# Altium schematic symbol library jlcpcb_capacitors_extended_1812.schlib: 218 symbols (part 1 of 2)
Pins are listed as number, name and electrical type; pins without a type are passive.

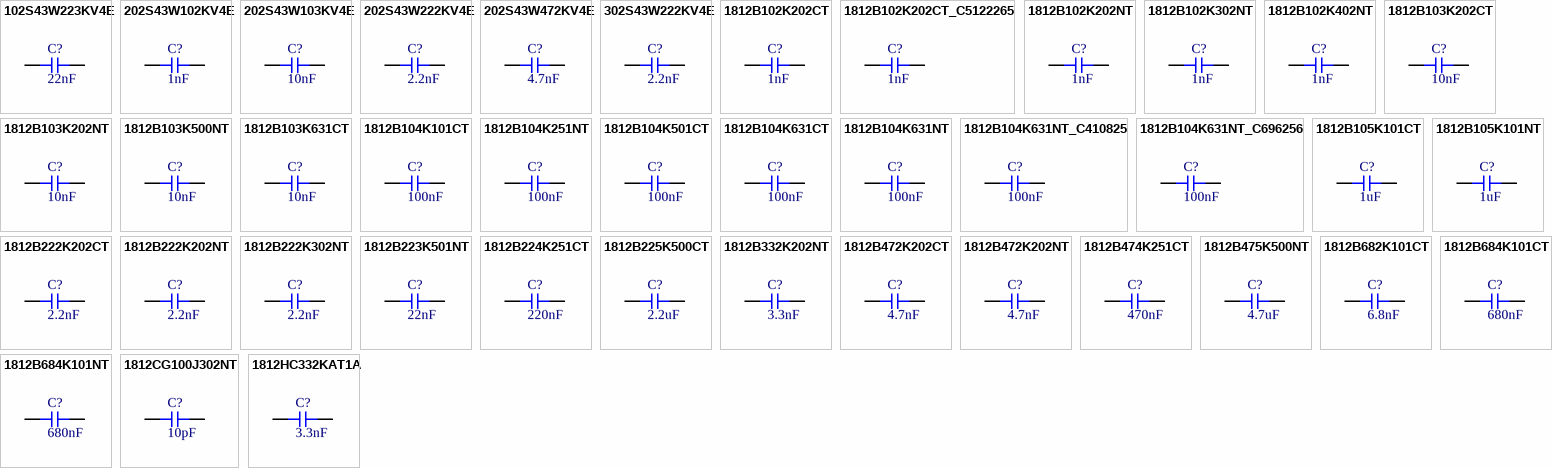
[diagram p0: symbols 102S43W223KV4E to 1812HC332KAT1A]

## 102S43W223KV4E
designator C?  Capacitance: 22nF  (hidden comment: *)
Capacitor, Ceramic (MLCC), 22nF, ±10%, 1kV, X7R, ±10%, SMD 1812; Manufacturer: Johanson Dielectrics; Manufacturer Part Number: 102S43W223KV4E
footprint CAP-1812 (1812 (4532M) Capacitor)
pins: 1, 2

## 202S43W102KV4E
designator C?  Capacitance: 1nF  (hidden comment: *)
Capacitor, Ceramic (MLCC), 1nF, ±10%, 2kV, X7R, ±10%, SMD 1812; Manufacturer: Johanson Dielectrics; Manufacturer Part Number: 202S43W102KV4E
footprint CAP-1812 (1812 (4532M) Capacitor)
pins: 1, 2

## 202S43W103KV4E
designator C?  Capacitance: 10nF  (hidden comment: *)
Capacitor, Ceramic (MLCC), 10nF, ±10%, 2kV, X7R, ±10%, SMD 1812; Manufacturer: Johanson Dielectrics; Manufacturer Part Number: 202S43W103KV4E
footprint CAP-1812 (1812 (4532M) Capacitor)
pins: 1, 2

## 202S43W222KV4E
designator C?  Capacitance: 2.2nF  (hidden comment: *)
Capacitor, Ceramic (MLCC), 2.2nF, ±10%, 2kV, X7R, ±10%, SMD 1812; Manufacturer: Johanson Dielectrics; Manufacturer Part Number: 202S43W222KV4E
footprint CAP-1812 (1812 (4532M) Capacitor)
pins: 1, 2

## 202S43W472KV4E
designator C?  Capacitance: 4.7nF  (hidden comment: *)
Capacitor, Ceramic (MLCC), 4.7nF, ±10%, 2kV, X7R, ±10%, SMD 1812; Manufacturer: Johanson Dielectrics; Manufacturer Part Number: 202S43W472KV4E
footprint CAP-1812 (1812 (4532M) Capacitor)
pins: 1, 2

## 302S43W222KV4E
designator C?  Capacitance: 2.2nF  (hidden comment: *)
Capacitor, Ceramic (MLCC), 2.2nF, ±10%, 3kV, X7R, ±10%, SMD 1812; Manufacturer: Johanson Dielectrics; Manufacturer Part Number: 302S43W222KV4E
footprint CAP-1812 (1812 (4532M) Capacitor)
pins: 1, 2

## 1812B102K202CT
designator C?  Capacitance: 1nF  (hidden comment: *)
Capacitor, Ceramic (MLCC), 1nF, ±10%, 2kV, X7R, ±10%, SMD 1812; Manufacturer: Walsin Tech Corp; Manufacturer Part Number: 1812B102K202CT
footprint CAP-1812 (1812 (4532M) Capacitor)
pins: 1, 2

## 1812B102K202CT_C5122265
designator C?  Capacitance: 1nF  (hidden comment: *)
Capacitor, Ceramic (MLCC), 1nF, ±10%, X7R, ±10%, SMD 1812; Manufacturer: Walsin Tech Corp; Manufacturer Part Number: 1812B102K202CT
footprint CAP-1812 (1812 (4532M) Capacitor)
pins: 1, 2

## 1812B102K202NT
designator C?  Capacitance: 1nF  (hidden comment: *)
Capacitor, Ceramic (MLCC), 1nF, ±10%, 2kV, X7R, ±10%, SMD 1812; Manufacturer: FH(Guangdong Fenghua Advanced Tech); Manufacturer Part Number: 1812B102K202NT
footprint CAP-1812 (1812 (4532M) Capacitor)
pins: 1, 2

## 1812B102K302NT
designator C?  Capacitance: 1nF  (hidden comment: *)
Capacitor, Ceramic (MLCC), 1nF, ±10%, 3kV, X7R, ±10%, SMD 1812; Manufacturer: FH (Guangdong Fenghua Advanced Tech); Manufacturer Part Number: 1812B102K302NT
footprint CAP-1812 (1812 (4532M) Capacitor)
pins: 1, 2

## 1812B102K402NT
designator C?  Capacitance: 1nF  (hidden comment: *)
Capacitor, Ceramic (MLCC), 1nF, ±10%, 4kV, X7R, ±10%, SMD 1812; Manufacturer: FH(Guangdong Fenghua Advanced Tech); Manufacturer Part Number: 1812B102K402NT
footprint CAP-1812 (1812 (4532M) Capacitor)
pins: 1, 2

## 1812B103K202CT
designator C?  Capacitance: 10nF  (hidden comment: *)
Capacitor, Ceramic (MLCC), 10nF, ±10%, 2kV, X7R, ±10%, SMD 1812; Manufacturer: Walsin Tech Corp; Manufacturer Part Number: 1812B103K202CT
footprint CAP-1812 (1812 (4532M) Capacitor)
pins: 1, 2

## 1812B103K202NT
designator C?  Capacitance: 10nF  (hidden comment: *)
Capacitor, Ceramic (MLCC), 10nF, ±10%, 2kV, X7R, ±10%, SMD 1812; Manufacturer: FH(Guangdong Fenghua Advanced Tech); Manufacturer Part Number: 1812B103K202NT
footprint CAP-1812 (1812 (4532M) Capacitor)
pins: 1, 2

## 1812B103K500NT
designator C?  Capacitance: 10nF  (hidden comment: *)
Capacitor, Ceramic (MLCC), 10nF, ±10%, 50V, ±10%, SMD 1812; Manufacturer: FH(Guangdong Fenghua Advanced Tech); Manufacturer Part Number: 1812B103K500NT
footprint CAP-1812 (1812 (4532M) Capacitor)
pins: 1, 2

## 1812B103K631CT
designator C?  Capacitance: 10nF  (hidden comment: *)
Capacitor, Ceramic (MLCC), 10nF, ±10%, 630V, X7R, ±10%, SMD 1812; Manufacturer: Walsin Tech Corp; Manufacturer Part Number: 1812B103K631CT
footprint CAP-1812 (1812 (4532M) Capacitor)
pins: 1, 2

## 1812B104K101CT
designator C?  Capacitance: 100nF  (hidden comment: *)
Capacitor, Ceramic (MLCC), 100nF, ±10%, 100V, X7R, ±10%, SMD 1812; Manufacturer: Walsin Tech Corp; Manufacturer Part Number: 1812B104K101CT
footprint CAP-1812 (1812 (4532M) Capacitor)
pins: 1, 2

## 1812B104K251NT
designator C?  Capacitance: 100nF  (hidden comment: *)
Capacitor, Ceramic (MLCC), 100nF, ±10%, 250V, X7R, ±10%, SMD 1812; Manufacturer: FH(Guangdong Fenghua Advanced Tech); Manufacturer Part Number: 1812B104K251NT
footprint CAP-1812 (1812 (4532M) Capacitor)
pins: 1, 2

## 1812B104K501CT
designator C?  Capacitance: 100nF  (hidden comment: *)
Capacitor, Ceramic (MLCC), 100nF, ±10%, 500V, X7R, ±10%, SMD 1812; Manufacturer: Walsin Tech Corp; Manufacturer Part Number: 1812B104K501CT
footprint CAP-1812 (1812 (4532M) Capacitor)
pins: 1, 2

## 1812B104K631CT
designator C?  Capacitance: 100nF  (hidden comment: *)
Capacitor, Ceramic (MLCC), 100nF, ±10%, 630V, X7R, ±10%, SMD 1812; Manufacturer: Walsin Tech Corp; Manufacturer Part Number: 1812B104K631CT
footprint CAP-1812 (1812 (4532M) Capacitor)
pins: 1, 2

## 1812B104K631NT
designator C?  Capacitance: 100nF  (hidden comment: *)
Capacitor, Ceramic (MLCC), 100nF, ±10%, 630V, X7R, ±10%, SMD 1812; Manufacturer: FH(Guangdong Fenghua Advanced Tech); Manufacturer Part Number: 1812B104K631NT
footprint CAP-1812 (1812 (4532M) Capacitor)
pins: 1, 2

## 1812B104K631NT_C410825
designator C?  Capacitance: 100nF  (hidden comment: *)
Capacitor, Ceramic (MLCC), 100nF, ±10%, 630V, X7R, ±10%, SMD 1812; Manufacturer: FH(Guangdong Fenghua Advanced Tech); Manufacturer Part Number: 1812B104K631NT
footprint CAP-1812 (1812 (4532M) Capacitor)
pins: 1, 2

## 1812B104K631NT_C696256
designator C?  Capacitance: 100nF  (hidden comment: *)
Capacitor, Ceramic (MLCC), 100nF, ±10%, 630V, X7R, ±10%, SMD 1812; Manufacturer: FH(Guangdong Fenghua Advanced Tech); Manufacturer Part Number: 1812B104K631NT
footprint CAP-1812 (1812 (4532M) Capacitor)
pins: 1, 2

## 1812B105K101CT
designator C?  Capacitance: 1uF  (hidden comment: *)
Capacitor, Ceramic (MLCC), 1uF, ±10%, 100V, X7R, ±10%, SMD 1812; Manufacturer: Walsin Tech Corp; Manufacturer Part Number: 1812B105K101CT
footprint CAP-1812 (1812 (4532M) Capacitor)
pins: 1, 2

## 1812B105K101NT
designator C?  Capacitance: 1uF  (hidden comment: *)
Capacitor, Ceramic (MLCC), 1uF, ±10%, 100V, X7R, ±10%, SMD 1812; Manufacturer: FH(Guangdong Fenghua Advanced Tech); Manufacturer Part Number: 1812B105K101NT
footprint CAP-1812 (1812 (4532M) Capacitor)
pins: 1, 2

## 1812B222K202CT
designator C?  Capacitance: 2.2nF  (hidden comment: *)
Capacitor, Ceramic (MLCC), 2.2nF, ±10%, 2kV, X7R, ±10%, SMD 1812; Manufacturer: Walsin Tech Corp; Manufacturer Part Number: 1812B222K202CT
footprint CAP-1812 (1812 (4532M) Capacitor)
pins: 1, 2

## 1812B222K202NT
designator C?  Capacitance: 2.2nF  (hidden comment: *)
Capacitor, Ceramic (MLCC), 2.2nF, ±10%, 2kV, X7R, ±10%, SMD 1812; Manufacturer: FH(Guangdong Fenghua Advanced Tech); Manufacturer Part Number: 1812B222K202NT
footprint CAP-1812 (1812 (4532M) Capacitor)
pins: 1, 2

## 1812B222K302NT
designator C?  Capacitance: 2.2nF  (hidden comment: *)
Capacitor, Ceramic (MLCC), 2.2nF, ±10%, 3kV, X7R, ±10%, SMD 1812; Manufacturer: FH(Guangdong Fenghua Advanced Tech); Manufacturer Part Number: 1812B222K302NT
footprint CAP-1812 (1812 (4532M) Capacitor)
pins: 1, 2

## 1812B223K501NT
designator C?  Capacitance: 22nF  (hidden comment: *)
Capacitor, Ceramic (MLCC), 22nF, ±10%, 500V, X7R, ±10%, SMD 1812; Manufacturer: FH(Guangdong Fenghua Advanced Tech); Manufacturer Part Number: 1812B223K501NT
footprint CAP-1812 (1812 (4532M) Capacitor)
pins: 1, 2

## 1812B224K251CT
designator C?  Capacitance: 220nF  (hidden comment: *)
Capacitor, Ceramic (MLCC), 220nF, ±10%, 250V, X7R, ±10%, SMD 1812; Manufacturer: Walsin Tech Corp; Manufacturer Part Number: 1812B224K251CT
footprint CAP-1812 (1812 (4532M) Capacitor)
pins: 1, 2

## 1812B225K500CT
designator C?  Capacitance: 2.2uF  (hidden comment: *)
Capacitor, Ceramic (MLCC), 2.2uF, ±10%, 50V, X7R, ±10%, SMD 1812; Manufacturer: Walsin Tech Corp; Manufacturer Part Number: 1812B225K500CT
footprint CAP-1812 (1812 (4532M) Capacitor)
pins: 1, 2

## 1812B332K202NT
designator C?  Capacitance: 3.3nF  (hidden comment: *)
Capacitor, Ceramic (MLCC), 3.3nF, ±10%, 2kV, ±10%, SMD 1812; Manufacturer: FH(Guangdong Fenghua Advanced Tech); Manufacturer Part Number: 1812B332K202NT
footprint CAP-1812 (1812 (4532M) Capacitor)
pins: 1, 2

## 1812B472K202CT
designator C?  Capacitance: 4.7nF  (hidden comment: *)
Capacitor, Ceramic (MLCC), 4.7nF, ±10%, 2kV, X7R, ±10%, SMD 1812; Manufacturer: Walsin Tech Corp; Manufacturer Part Number: 1812B472K202CT
footprint CAP-1812 (1812 (4532M) Capacitor)
pins: 1, 2

## 1812B472K202NT
designator C?  Capacitance: 4.7nF  (hidden comment: *)
Capacitor, Ceramic (MLCC), 4.7nF, ±10%, 2kV, ±10%, SMD 1812; Manufacturer: FH(Guangdong Fenghua Advanced Tech); Manufacturer Part Number: 1812B472K202NT
footprint CAP-1812 (1812 (4532M) Capacitor)
pins: 1, 2

## 1812B474K251CT
designator C?  Capacitance: 470nF  (hidden comment: *)
Capacitor, Ceramic (MLCC), 470nF, ±10%, 250V, X7R, ±10%, SMD 1812; Manufacturer: Walsin Tech Corp; Manufacturer Part Number: 1812B474K251CT
footprint CAP-1812 (1812 (4532M) Capacitor)
pins: 1, 2

## 1812B475K500NT
designator C?  Capacitance: 4.7uF  (hidden comment: *)
Capacitor, Ceramic (MLCC), 4.7uF, ±10%, 50V, X7R, ±10%, SMD 1812; Manufacturer: FH(Guangdong Fenghua Advanced Tech); Manufacturer Part Number: 1812B475K500NT
footprint CAP-1812 (1812 (4532M) Capacitor)
pins: 1, 2

## 1812B682K101CT
designator C?  Capacitance: 6.8nF  (hidden comment: *)
Capacitor, Ceramic (MLCC), 6.8nF, ±10%, 100V, X7R, ±10%, SMD 1812; Manufacturer: Walsin Tech Corp; Manufacturer Part Number: 1812B682K101CT
footprint CAP-1812 (1812 (4532M) Capacitor)
pins: 1, 2

## 1812B684K101CT
designator C?  Capacitance: 680nF  (hidden comment: *)
Capacitor, Ceramic (MLCC), 680nF, ±10%, 100V, X7R, ±10%, SMD 1812; Manufacturer: Walsin Tech Corp; Manufacturer Part Number: 1812B684K101CT
footprint CAP-1812 (1812 (4532M) Capacitor)
pins: 1, 2

## 1812B684K101NT
designator C?  Capacitance: 680nF  (hidden comment: *)
Capacitor, Ceramic (MLCC), 680nF, ±10%, 100V, X7R, ±10%, SMD 1812; Manufacturer: FH(Guangdong Fenghua Advanced Tech); Manufacturer Part Number: 1812B684K101NT
footprint CAP-1812 (1812 (4532M) Capacitor)
pins: 1, 2

## 1812CG100J302NT
designator C?  Capacitance: 10pF  (hidden comment: *)
Capacitor, Ceramic (MLCC), 10pF, ±5%, 3kV, C0G, ±5%, SMD 1812; Manufacturer: FH(Guangdong Fenghua Advanced Tech); Manufacturer Part Number: 1812CG100J302NT
footprint CAP-1812 (1812 (4532M) Capacitor)
pins: 1, 2

## 1812HC332KAT1A
designator C?  Capacitance: 3.3nF  (hidden comment: *)
Capacitor, Ceramic (MLCC), 3.3nF, ±10%, 3kV, X7R, ±10%, SMD 1812; Manufacturer: AVX; Manufacturer Part Number: 1812HC332KAT1A
footprint CAP-1812 (1812 (4532M) Capacitor)
pins: 1, 2

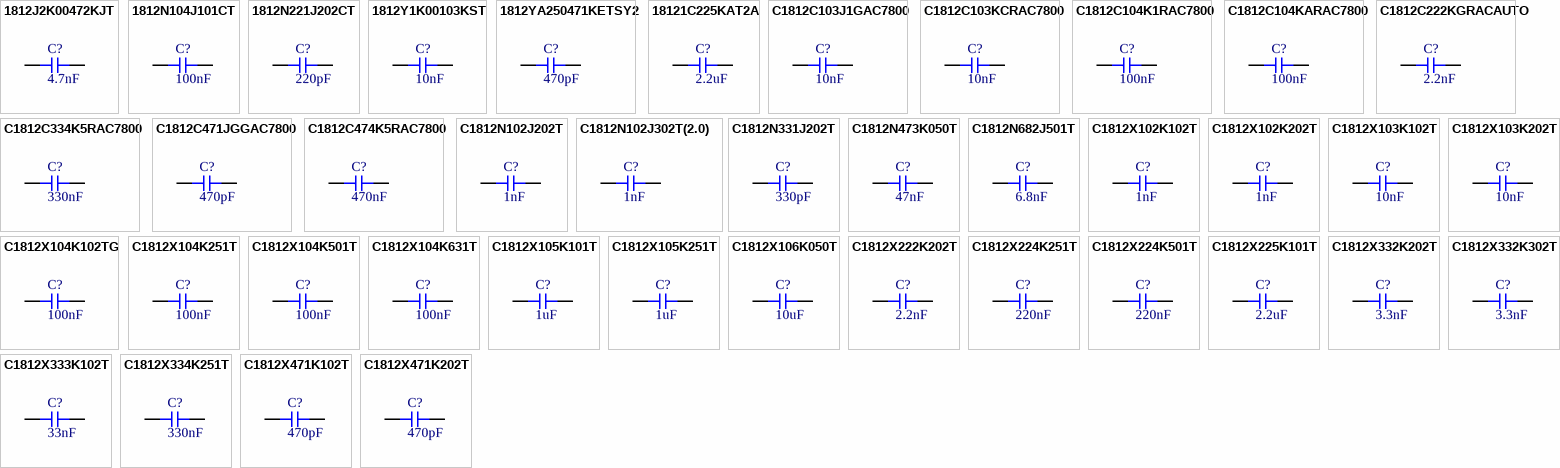
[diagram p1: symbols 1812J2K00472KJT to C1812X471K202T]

## 1812J2K00472KJT
designator C?  Capacitance: 4.7nF  (hidden comment: *)
Capacitor, Ceramic (MLCC), 4.7nF, ±10%, 2kV, X7R, ±10%, SMD 1812; Manufacturer: Knowles; Manufacturer Part Number: 1812J2K00472KJT
footprint CAP-1812 (1812 (4532M) Capacitor)
pins: 1, 2

## 1812N104J101CT
designator C?  Capacitance: 100nF  (hidden comment: *)
Capacitor, Ceramic (MLCC), 100nF, ±5%, 100V, NP0, ±5%, SMD 1812; Manufacturer: Walsin Tech Corp; Manufacturer Part Number: 1812N104J101CT
footprint CAP-1812 (1812 (4532M) Capacitor)
pins: 1, 2

## 1812N221J202CT
designator C?  Capacitance: 220pF  (hidden comment: *)
Capacitor, Ceramic (MLCC), 220pF, ±5%, 2kV, NP0, ±5%, SMD 1812; Manufacturer: Walsin Tech Corp; Manufacturer Part Number: 1812N221J202CT
footprint CAP-1812 (1812 (4532M) Capacitor)
pins: 1, 2

## 1812Y1K00103KST
designator C?  Capacitance: 10nF  (hidden comment: *)
Capacitor, Ceramic (MLCC), 10nF, ±10%, 1kV, X7R, ±10%, SMD 1812; Manufacturer: Knowles; Manufacturer Part Number: 1812Y1K00103KST
footprint CAP-1812 (1812 (4532M) Capacitor)
pins: 1, 2

## 1812YA250471KETSY2
designator C?  Capacitance: 470pF  (hidden comment: *)
Capacitor, Ceramic (MLCC), 470pF, ±10%, 2.5kV, X7R, ±10%, SMD 1812; Manufacturer: Knowles; Manufacturer Part Number: 1812YA250471KETSY2
footprint CAP-1812 (1812 (4532M) Capacitor)
pins: 1, 2

## 18121C225KAT2A
designator C?  Capacitance: 2.2uF  (hidden comment: *)
Capacitor, Ceramic (MLCC), 2.2uF, ±10%, 100V, X7R, ±10%, SMD 1812; Manufacturer: AVX; Manufacturer Part Number: 18121C225KAT2A
footprint CAP-1812 (1812 (4532M) Capacitor)
pins: 1, 2

## C1812C103J1GAC7800
designator C?  Capacitance: 10nF  (hidden comment: *)
Capacitor, Ceramic (MLCC), 10nF, ±5%, 100V, C0G, ±5%, SMD 1812; Manufacturer: KEMET; Manufacturer Part Number: C1812C103J1GAC7800
footprint CAP-1812 (1812 (4532M) Capacitor)
pins: 1, 2

## C1812C103KCRAC7800
designator C?  Capacitance: 10nF  (hidden comment: *)
Capacitor, Ceramic (MLCC), 10nF, ±10%, 500V, X7R, ±10%, SMD 1812; Manufacturer: KEMET; Manufacturer Part Number: C1812C103KCRAC7800
footprint CAP-1812 (1812 (4532M) Capacitor)
pins: 1, 2

## C1812C104K1RAC7800
designator C?  Capacitance: 100nF  (hidden comment: *)
Capacitor, Ceramic (MLCC), 100nF, ±10%, 100V, X7R, ±10%, SMD 1812; Manufacturer: KEMET; Manufacturer Part Number: C1812C104K1RAC7800
footprint CAP-1812 (1812 (4532M) Capacitor)
pins: 1, 2

## C1812C104KARAC7800
designator C?  Capacitance: 100nF  (hidden comment: *)
Capacitor, Ceramic (MLCC), 100nF, ±10%, 250V, X7R, ±10%, SMD 1812; Manufacturer: KEMET; Manufacturer Part Number: C1812C104KARAC7800
footprint CAP-1812 (1812 (4532M) Capacitor)
pins: 1, 2

## C1812C222KGRACAUTO
designator C?  Capacitance: 2.2nF  (hidden comment: *)
Capacitor, Ceramic (MLCC), 2.2nF, ±10%, 2kV, X7R, ±10%, SMD 1812; Manufacturer: KEMET; Manufacturer Part Number: C1812C222KGRACAUTO
footprint CAP-1812 (1812 (4532M) Capacitor)
pins: 1, 2

## C1812C334K5RAC7800
designator C?  Capacitance: 330nF  (hidden comment: *)
Capacitor, Ceramic (MLCC), 330nF, ±10%, 50V, X7R, ±10%, SMD 1812; Manufacturer: KEMET; Manufacturer Part Number: C1812C334K5RAC7800
footprint CAP-1812 (1812 (4532M) Capacitor)
pins: 1, 2

## C1812C471JGGAC7800
designator C?  Capacitance: 470pF  (hidden comment: *)
Capacitor, Ceramic (MLCC), 470pF, ±5%, 2kV, C0G, ±5%, SMD 1812; Manufacturer: KEMET; Manufacturer Part Number: C1812C471JGGAC7800
footprint CAP-1812 (1812 (4532M) Capacitor)
pins: 1, 2

## C1812C474K5RAC7800
designator C?  Capacitance: 470nF  (hidden comment: *)
Capacitor, Ceramic (MLCC), 470nF, ±10%, 50V, X7R, ±10%, SMD 1812; Manufacturer: KEMET; Manufacturer Part Number: C1812C474K5RAC7800
footprint CAP-1812 (1812 (4532M) Capacitor)
pins: 1, 2

## C1812N102J202T
designator C?  Capacitance: 1nF  (hidden comment: *)
Capacitor, Ceramic (MLCC), 1nF, ±5%, 2kV, C0G, ±5%, SMD 1812; Manufacturer: IHHEC(HOLY STONE ENTERPRISE CO., LTD); Manufacturer Part Number: C1812N102J202T
footprint CAP-1812 (1812 (4532M) Capacitor)
pins: 1, 2

## C1812N102J302T(2.0)
designator C?  Capacitance: 1nF  (hidden comment: *)
Capacitor, Ceramic (MLCC), 1nF, ±5%, 3kV, NP0, ±5%, SMD 1812; Manufacturer: IHHEC(HOLY STONE ENTERPRISE CO., LTD); Manufacturer Part Number: C1812N102J302T(2.0)
footprint CAP-1812 (1812 (4532M) Capacitor)
pins: 1, 2

## C1812N331J202T
designator C?  Capacitance: 330pF  (hidden comment: *)
Capacitor, Ceramic (MLCC), 330pF, ±5%, 2kV, C0G, ±5%, SMD 1812; Manufacturer: IHHEC(HOLY STONE ENTERPRISE CO., LTD); Manufacturer Part Number: C1812N331J202T
footprint CAP-1812 (1812 (4532M) Capacitor)
pins: 1, 2

## C1812N473K050T
designator C?  Capacitance: 47nF  (hidden comment: *)
Capacitor, Ceramic (MLCC), 47nF, ±10%, 50V, NP0, ±10%, SMD 1812; Manufacturer: IHHEC(HOLY STONE ENTERPRISE CO., LTD); Manufacturer Part Number: C1812N473K050T
footprint CAP-1812 (1812 (4532M) Capacitor)
pins: 1, 2

## C1812N682J501T
designator C?  Capacitance: 6.8nF  (hidden comment: *)
Capacitor, Ceramic (MLCC), 6.8nF, ±5%, 500V, NP0, ±5%, SMD 1812; Manufacturer: IHHEC(HOLY STONE ENTERPRISE CO., LTD); Manufacturer Part Number: C1812N682J501T
footprint CAP-1812 (1812 (4532M) Capacitor)
pins: 1, 2

## C1812X102K102T
designator C?  Capacitance: 1nF  (hidden comment: *)
Capacitor, Ceramic (MLCC), 1nF, ±10%, 1kV, X7R, ±10%, SMD 1812; Manufacturer: IHHEC(HOLY STONE ENTERPRISE CO., LTD); Manufacturer Part Number: C1812X102K102T
footprint CAP-1812 (1812 (4532M) Capacitor)
pins: 1, 2

## C1812X102K202T
designator C?  Capacitance: 1nF  (hidden comment: *)
Capacitor, Ceramic (MLCC), 1nF, ±10%, 2kV, X7R, ±10%, SMD 1812; Manufacturer: IHHEC(HOLY STONE ENTERPRISE CO., LTD); Manufacturer Part Number: C1812X102K202T
footprint CAP-1812 (1812 (4532M) Capacitor)
pins: 1, 2

## C1812X103K102T
designator C?  Capacitance: 10nF  (hidden comment: *)
Capacitor, Ceramic (MLCC), 10nF, ±10%, 1kV, X7R, ±10%, SMD 1812; Manufacturer: IHHEC(HOLY STONE ENTERPRISE CO., LTD); Manufacturer Part Number: C1812X103K102T
footprint CAP-1812 (1812 (4532M) Capacitor)
pins: 1, 2

## C1812X103K202T
designator C?  Capacitance: 10nF  (hidden comment: *)
Capacitor, Ceramic (MLCC), 10nF, ±10%, 2kV, X7R, ±10%, SMD 1812; Manufacturer: IHHEC(HOLY STONE ENTERPRISE CO., LTD); Manufacturer Part Number: C1812X103K202T
footprint CAP-1812 (1812 (4532M) Capacitor)
pins: 1, 2

## C1812X104K102TG
designator C?  Capacitance: 100nF  (hidden comment: *)
Capacitor, Ceramic (MLCC), 100nF, ±10%, 1kV, X7R, ±10%, SMD 1812; Manufacturer: IHHEC(HOLY STONE ENTERPRISE CO., LTD); Manufacturer Part Number: C1812X104K102TG
footprint CAP-1812 (1812 (4532M) Capacitor)
pins: 1, 2

## C1812X104K251T
designator C?  Capacitance: 100nF  (hidden comment: *)
Capacitor, Ceramic (MLCC), 100nF, ±10%, 250V, X7R, ±10%, SMD 1812; Manufacturer: IHHEC(HOLY STONE ENTERPRISE CO., LTD); Manufacturer Part Number: C1812X104K251T
footprint CAP-1812 (1812 (4532M) Capacitor)
pins: 1, 2

## C1812X104K501T
designator C?  Capacitance: 100nF  (hidden comment: *)
Capacitor, Ceramic (MLCC), 100nF, ±10%, 500V, X7R, ±10%, SMD 1812; Manufacturer: IHHEC(HOLY STONE ENTERPRISE CO., LTD); Manufacturer Part Number: C1812X104K501T
footprint CAP-1812 (1812 (4532M) Capacitor)
pins: 1, 2

## C1812X104K631T
designator C?  Capacitance: 100nF  (hidden comment: *)
Capacitor, Ceramic (MLCC), 100nF, ±10%, 630V, X7R, ±10%, SMD 1812; Manufacturer: IHHEC(HOLY STONE ENTERPRISE CO., LTD); Manufacturer Part Number: C1812X104K631T
footprint CAP-1812 (1812 (4532M) Capacitor)
pins: 1, 2

## C1812X105K101T
designator C?  Capacitance: 1uF  (hidden comment: *)
Capacitor, Ceramic (MLCC), 1uF, ±10%, 100V, X7R, ±10%, SMD 1812; Manufacturer: IHHEC(HOLY STONE ENTERPRISE CO., LTD); Manufacturer Part Number: C1812X105K101T
footprint CAP-1812 (1812 (4532M) Capacitor)
pins: 1, 2

## C1812X105K251T
designator C?  Capacitance: 1uF  (hidden comment: *)
Capacitor, Ceramic (MLCC), 1uF, ±10%, 250V, X7R, ±10%, SMD 1812; Manufacturer: IHHEC(HOLY STONE ENTERPRISE CO., LTD); Manufacturer Part Number: C1812X105K251T
footprint CAP-1812 (1812 (4532M) Capacitor)
pins: 1, 2

## C1812X106K050T
designator C?  Capacitance: 10uF  (hidden comment: *)
Capacitor, Ceramic (MLCC), 10uF, ±10%, 50V, X7R, ±10%, SMD 1812; Manufacturer: IHHEC(HOLY STONE ENTERPRISE CO., LTD); Manufacturer Part Number: C1812X106K050T
footprint CAP-1812 (1812 (4532M) Capacitor)
pins: 1, 2

## C1812X222K202T
designator C?  Capacitance: 2.2nF  (hidden comment: *)
Capacitor, Ceramic (MLCC), 2.2nF, ±10%, 2kV, X7R, ±10%, SMD 1812; Manufacturer: IHHEC(HOLY STONE ENTERPRISE CO., LTD); Manufacturer Part Number: C1812X222K202T
footprint CAP-1812 (1812 (4532M) Capacitor)
pins: 1, 2

## C1812X224K251T
designator C?  Capacitance: 220nF  (hidden comment: *)
Capacitor, Ceramic (MLCC), 220nF, ±10%, 250V, X7R, ±10%, SMD 1812; Manufacturer: IHHEC(HOLY STONE ENTERPRISE CO., LTD); Manufacturer Part Number: C1812X224K251T
footprint CAP-1812 (1812 (4532M) Capacitor)
pins: 1, 2

## C1812X224K501T
designator C?  Capacitance: 220nF  (hidden comment: *)
Capacitor, Ceramic (MLCC), 220nF, ±10%, 500V, X7R, ±10%, SMD 1812; Manufacturer: IHHEC(HOLY STONE ENTERPRISE CO., LTD); Manufacturer Part Number: C1812X224K501T
footprint CAP-1812 (1812 (4532M) Capacitor)
pins: 1, 2

## C1812X225K101T
designator C?  Capacitance: 2.2uF  (hidden comment: *)
Capacitor, Ceramic (MLCC), 2.2uF, ±10%, 100V, X7R, ±10%, SMD 1812; Manufacturer: IHHEC(HOLY STONE ENTERPRISE CO., LTD); Manufacturer Part Number: C1812X225K101T
footprint CAP-1812 (1812 (4532M) Capacitor)
pins: 1, 2

## C1812X332K202T
designator C?  Capacitance: 3.3nF  (hidden comment: *)
Capacitor, Ceramic (MLCC), 3.3nF, ±10%, 2kV, X7R, ±10%, SMD 1812; Manufacturer: IHHEC(HOLY STONE ENTERPRISE CO., LTD); Manufacturer Part Number: C1812X332K202T
footprint CAP-1812 (1812 (4532M) Capacitor)
pins: 1, 2

## C1812X332K302T
designator C?  Capacitance: 3.3nF  (hidden comment: *)
Capacitor, Ceramic (MLCC), 3.3nF, ±10%, 3kV, X7R, ±10%, SMD 1812; Manufacturer: IHHEC(HOLY STONE ENTERPRISE CO., LTD); Manufacturer Part Number: C1812X332K302T
footprint CAP-1812 (1812 (4532M) Capacitor)
pins: 1, 2

## C1812X333K102T
designator C?  Capacitance: 33nF  (hidden comment: *)
Capacitor, Ceramic (MLCC), 33nF, ±10%, 1kV, X7R, ±10%, SMD 1812; Manufacturer: IHHEC(HOLY STONE ENTERPRISE CO., LTD); Manufacturer Part Number: C1812X333K102T
footprint CAP-1812 (1812 (4532M) Capacitor)
pins: 1, 2

## C1812X334K251T
designator C?  Capacitance: 330nF  (hidden comment: *)
Capacitor, Ceramic (MLCC), 330nF, ±10%, 250V, X7R, ±10%, SMD 1812; Manufacturer: IHHEC(HOLY STONE ENTERPRISE CO., LTD); Manufacturer Part Number: C1812X334K251T
footprint CAP-1812 (1812 (4532M) Capacitor)
pins: 1, 2

## C1812X471K102T
designator C?  Capacitance: 470pF  (hidden comment: *)
Capacitor, Ceramic (MLCC), 470pF, ±10%, 1kV, X7R, ±10%, SMD 1812; Manufacturer: IHHEC(HOLY STONE ENTERPRISE CO., LTD); Manufacturer Part Number: C1812X471K102T
footprint CAP-1812 (1812 (4532M) Capacitor)
pins: 1, 2

## C1812X471K202T
designator C?  Capacitance: 470pF  (hidden comment: *)
Capacitor, Ceramic (MLCC), 470pF, ±10%, 2kV, X7R, ±10%, SMD 1812; Manufacturer: IHHEC(HOLY STONE ENTERPRISE CO., LTD); Manufacturer Part Number: C1812X471K202T
footprint CAP-1812 (1812 (4532M) Capacitor)
pins: 1, 2

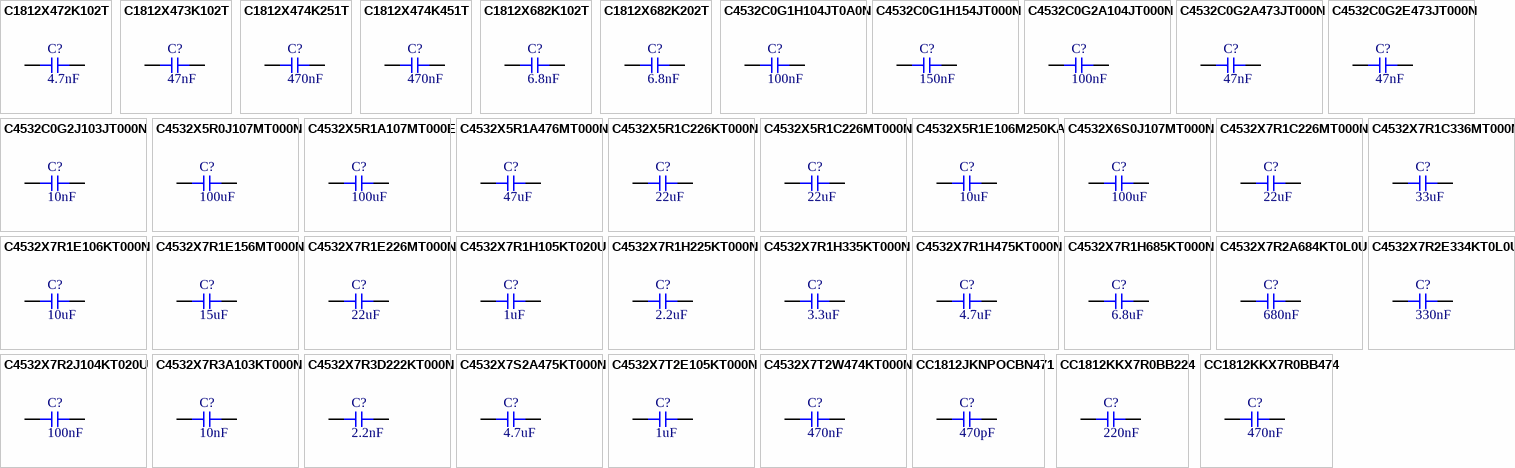
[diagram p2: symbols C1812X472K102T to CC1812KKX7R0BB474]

## C1812X472K102T
designator C?  Capacitance: 4.7nF  (hidden comment: *)
Capacitor, Ceramic (MLCC), 4.7nF, ±10%, 1kV, X7R, ±10%, SMD 1812; Manufacturer: IHHEC(HOLY STONE ENTERPRISE CO., LTD); Manufacturer Part Number: C1812X472K102T
footprint CAP-1812 (1812 (4532M) Capacitor)
pins: 1, 2

## C1812X473K102T
designator C?  Capacitance: 47nF  (hidden comment: *)
Capacitor, Ceramic (MLCC), 47nF, ±10%, 1kV, X7R, ±10%, SMD 1812; Manufacturer: IHHEC(HOLY STONE ENTERPRISE CO., LTD); Manufacturer Part Number: C1812X473K102T
footprint CAP-1812 (1812 (4532M) Capacitor)
pins: 1, 2

## C1812X474K251T
designator C?  Capacitance: 470nF  (hidden comment: *)
Capacitor, Ceramic (MLCC), 470nF, ±10%, 250V, X7R, ±10%, SMD 1812; Manufacturer: IHHEC(HOLY STONE ENTERPRISE CO., LTD); Manufacturer Part Number: C1812X474K251T
footprint CAP-1812 (1812 (4532M) Capacitor)
pins: 1, 2

## C1812X474K451T
designator C?  Capacitance: 470nF  (hidden comment: *)
Capacitor, Ceramic (MLCC), 470nF, ±10%, 450V, X7R, ±10%, SMD 1812; Manufacturer: IHHEC(HOLY STONE ENTERPRISE CO., LTD); Manufacturer Part Number: C1812X474K451T
footprint CAP-1812 (1812 (4532M) Capacitor)
pins: 1, 2

## C1812X682K102T
designator C?  Capacitance: 6.8nF  (hidden comment: *)
Capacitor, Ceramic (MLCC), 6.8nF, ±10%, 1kV, X7R, ±10%, SMD 1812; Manufacturer: IHHEC(HOLY STONE ENTERPRISE CO., LTD); Manufacturer Part Number: C1812X682K102T
footprint CAP-1812 (1812 (4532M) Capacitor)
pins: 1, 2

## C1812X682K202T
designator C?  Capacitance: 6.8nF  (hidden comment: *)
Capacitor, Ceramic (MLCC), 6.8nF, ±10%, 2kV, X7R, ±10%, SMD 1812; Manufacturer: IHHEC(HOLY STONE ENTERPRISE CO., LTD); Manufacturer Part Number: C1812X682K202T
footprint CAP-1812 (1812 (4532M) Capacitor)
pins: 1, 2

## C4532C0G1H104JT0A0N
designator C?  Capacitance: 100nF  (hidden comment: *)
Capacitor, Ceramic (MLCC), 100nF, ±5%, 50V, C0G, ±5%, SMD 1812; Manufacturer: TDK; Manufacturer Part Number: C4532C0G1H104JT0A0N
footprint CAP-1812 (1812 (4532M) Capacitor)
pins: 1, 2

## C4532C0G1H154JT000N
designator C?  Capacitance: 150nF  (hidden comment: *)
Capacitor, Ceramic (MLCC), 150nF, ±5%, 50V, C0G, ±5%, SMD 1812; Manufacturer: TDK; Manufacturer Part Number: C4532C0G1H154JT000N
footprint CAP-1812 (1812 (4532M) Capacitor)
pins: 1, 2

## C4532C0G2A104JT000N
designator C?  Capacitance: 100nF  (hidden comment: *)
Capacitor, Ceramic (MLCC), 100nF, ±5%, 100V, C0G, ±5%, SMD 1812; Manufacturer: TDK; Manufacturer Part Number: C4532C0G2A104JT000N
footprint CAP-1812 (1812 (4532M) Capacitor)
pins: 1, 2

## C4532C0G2A473JT000N
designator C?  Capacitance: 47nF  (hidden comment: *)
Capacitor, Ceramic (MLCC), 47nF, ±5%, 100V, C0G, ±5%, SMD 1812; Manufacturer: TDK; Manufacturer Part Number: C4532C0G2A473JT000N
footprint CAP-1812 (1812 (4532M) Capacitor)
pins: 1, 2

## C4532C0G2E473JT000N
designator C?  Capacitance: 47nF  (hidden comment: *)
Capacitor, Ceramic (MLCC), 47nF, ±5%, 250V, C0G, ±5%, SMD 1812; Manufacturer: TDK; Manufacturer Part Number: C4532C0G2E473JT000N
footprint CAP-1812 (1812 (4532M) Capacitor)
pins: 1, 2

## C4532C0G2J103JT000N
designator C?  Capacitance: 10nF  (hidden comment: *)
Capacitor, Ceramic (MLCC), 10nF, ±5%, 630V, C0G, ±5%, SMD 1812; Manufacturer: TDK; Manufacturer Part Number: C4532C0G2J103JT000N
footprint CAP-1812 (1812 (4532M) Capacitor)
pins: 1, 2

## C4532X5R0J107MT000N
designator C?  Capacitance: 100uF  (hidden comment: *)
Capacitor, Ceramic (MLCC), 100uF, ±20%, 6.3V, X5R, ±20%, SMD 1812; Manufacturer: TDK; Manufacturer Part Number: C4532X5R0J107MT000N
footprint CAP-1812 (1812 (4532M) Capacitor)
pins: 1, 2

## C4532X5R1A107MT000E
designator C?  Capacitance: 100uF  (hidden comment: *)
Capacitor, Ceramic (MLCC), 100uF, ±20%, 10V, X5R, ±20%, SMD 1812; Manufacturer: TDK; Manufacturer Part Number: C4532X5R1A107MT000E
footprint CAP-1812 (1812 (4532M) Capacitor)
pins: 1, 2

## C4532X5R1A476MT000N
designator C?  Capacitance: 47uF  (hidden comment: *)
Capacitor, Ceramic (MLCC), 47uF, ±20%, 10V, X5R, ±20%, SMD 1812; Manufacturer: TDK; Manufacturer Part Number: C4532X5R1A476MT000N
footprint CAP-1812 (1812 (4532M) Capacitor)
pins: 1, 2

## C4532X5R1C226KT000N
designator C?  Capacitance: 22uF  (hidden comment: *)
Capacitor, Ceramic (MLCC), 22uF, ±10%, 16V, X5R, ±10%, SMD 1812; Manufacturer: TDK; Manufacturer Part Number: C4532X5R1C226KT000N
footprint CAP-1812 (1812 (4532M) Capacitor)
pins: 1, 2

## C4532X5R1C226MT000N
designator C?  Capacitance: 22uF  (hidden comment: *)
Capacitor, Ceramic (MLCC), 22uF, ±20%, 16V, X5R, ±20%, SMD 1812; Manufacturer: TDK; Manufacturer Part Number: C4532X5R1C226MT000N
footprint CAP-1812 (1812 (4532M) Capacitor)
pins: 1, 2

## C4532X5R1E106M250KA
designator C?  Capacitance: 10uF  (hidden comment: *)
Capacitor, Ceramic (MLCC), 10uF, ±20%, 25V, X5R, ±20%, SMD 1812; Manufacturer: TDK; Manufacturer Part Number: C4532X5R1E106M250KA
footprint CAP-1812 (1812 (4532M) Capacitor)
pins: 1, 2

## C4532X6S0J107MT000N
designator C?  Capacitance: 100uF  (hidden comment: *)
Capacitor, Ceramic (MLCC), 100uF, ±20%, 6.3V, X6S, ±20%, SMD 1812; Manufacturer: TDK; Manufacturer Part Number: C4532X6S0J107MT000N
footprint CAP-1812 (1812 (4532M) Capacitor)
pins: 1, 2

## C4532X7R1C226MT000N
designator C?  Capacitance: 22uF  (hidden comment: *)
Capacitor, Ceramic (MLCC), 22uF, ±20%, 16V, X7R, ±20%, SMD 1812; Manufacturer: TDK; Manufacturer Part Number: C4532X7R1C226MT000N
footprint CAP-1812 (1812 (4532M) Capacitor)
pins: 1, 2

## C4532X7R1C336MT000N
designator C?  Capacitance: 33uF  (hidden comment: *)
Capacitor, Ceramic (MLCC), 33uF, ±20%, 16V, X7R, ±20%, SMD 1812; Manufacturer: TDK; Manufacturer Part Number: C4532X7R1C336MT000N
footprint CAP-1812 (1812 (4532M) Capacitor)
pins: 1, 2

## C4532X7R1E106KT000N
designator C?  Capacitance: 10uF  (hidden comment: *)
Capacitor, Ceramic (MLCC), 10uF, ±10%, 25V, X7R, ±10%, SMD 1812; Manufacturer: TDK; Manufacturer Part Number: C4532X7R1E106KT000N
footprint CAP-1812 (1812 (4532M) Capacitor)
pins: 1, 2

## C4532X7R1E156MT000N
designator C?  Capacitance: 15uF  (hidden comment: *)
Capacitor, Ceramic (MLCC), 15uF, ±20%, 25V, X7R, ±20%, SMD 1812; Manufacturer: TDK; Manufacturer Part Number: C4532X7R1E156MT000N
footprint CAP-1812 (1812 (4532M) Capacitor)
pins: 1, 2

## C4532X7R1E226MT000N
designator C?  Capacitance: 22uF  (hidden comment: *)
Capacitor, Ceramic (MLCC), 22uF, ±20%, 25V, X7R, ±20%, SMD 1812; Manufacturer: TDK; Manufacturer Part Number: C4532X7R1E226MT000N
footprint CAP-1812 (1812 (4532M) Capacitor)
pins: 1, 2

## C4532X7R1H105KT020U
designator C?  Capacitance: 1uF  (hidden comment: *)
Capacitor, Ceramic (MLCC), 1uF, ±10%, 50V, X7R, ±10%, SMD 1812; Manufacturer: TDK; Manufacturer Part Number: C4532X7R1H105KT020U
footprint CAP-1812 (1812 (4532M) Capacitor)
pins: 1, 2

## C4532X7R1H225KT000N
designator C?  Capacitance: 2.2uF  (hidden comment: *)
Capacitor, Ceramic (MLCC), 2.2uF, ±10%, 50V, X7R, ±10%, SMD 1812; Manufacturer: TDK; Manufacturer Part Number: C4532X7R1H225KT000N
footprint CAP-1812 (1812 (4532M) Capacitor)
pins: 1, 2

## C4532X7R1H335KT000N
designator C?  Capacitance: 3.3uF  (hidden comment: *)
Capacitor, Ceramic (MLCC), 3.3uF, ±10%, 50V, X7R, ±10%, SMD 1812; Manufacturer: TDK; Manufacturer Part Number: C4532X7R1H335KT000N
footprint CAP-1812 (1812 (4532M) Capacitor)
pins: 1, 2

## C4532X7R1H475KT000N
designator C?  Capacitance: 4.7uF  (hidden comment: *)
Capacitor, Ceramic (MLCC), 4.7uF, ±10%, 50V, X7R, ±10%, SMD 1812; Manufacturer: TDK; Manufacturer Part Number: C4532X7R1H475KT000N
footprint CAP-1812 (1812 (4532M) Capacitor)
pins: 1, 2

## C4532X7R1H685KT000N
designator C?  Capacitance: 6.8uF  (hidden comment: *)
Capacitor, Ceramic (MLCC), 6.8uF, ±10%, 50V, X7R, ±10%, SMD 1812; Manufacturer: TDK; Manufacturer Part Number: C4532X7R1H685KT000N
footprint CAP-1812 (1812 (4532M) Capacitor)
pins: 1, 2

## C4532X7R2A684KT0L0U
designator C?  Capacitance: 680nF  (hidden comment: *)
Capacitor, Ceramic (MLCC), 680nF, ±10%, 100V, X7R, ±10%, SMD 1812; Manufacturer: TDK; Manufacturer Part Number: C4532X7R2A684KT0L0U
footprint CAP-1812 (1812 (4532M) Capacitor)
pins: 1, 2

## C4532X7R2E334KT0L0U
designator C?  Capacitance: 330nF  (hidden comment: *)
Capacitor, Ceramic (MLCC), 330nF, ±10%, 250V, X7R, ±10%, SMD 1812; Manufacturer: TDK; Manufacturer Part Number: C4532X7R2E334KT0L0U
footprint CAP-1812 (1812 (4532M) Capacitor)
pins: 1, 2

## C4532X7R2J104KT020U
designator C?  Capacitance: 100nF  (hidden comment: *)
Capacitor, Ceramic (MLCC), 100nF, ±10%, 630V, X7R, ±10%, SMD 1812; Manufacturer: TDK; Manufacturer Part Number: C4532X7R2J104KT020U
footprint CAP-1812 (1812 (4532M) Capacitor)
pins: 1, 2

## C4532X7R3A103KT000N
designator C?  Capacitance: 10nF  (hidden comment: *)
Capacitor, Ceramic (MLCC), 10nF, ±10%, 1kV, X7R, ±10%, SMD 1812; Manufacturer: TDK; Manufacturer Part Number: C4532X7R3A103KT000N
footprint CAP-1812 (1812 (4532M) Capacitor)
pins: 1, 2

## C4532X7R3D222KT000N
designator C?  Capacitance: 2.2nF  (hidden comment: *)
Capacitor, Ceramic (MLCC), 2.2nF, ±10%, 2kV, X7R, ±10%, SMD 1812; Manufacturer: TDK; Manufacturer Part Number: C4532X7R3D222KT000N
footprint CAP-1812 (1812 (4532M) Capacitor)
pins: 1, 2

## C4532X7S2A475KT000N
designator C?  Capacitance: 4.7uF  (hidden comment: *)
Capacitor, Ceramic (MLCC), 4.7uF, ±10%, 100V, X7S, ±10%, SMD 1812; Manufacturer: TDK; Manufacturer Part Number: C4532X7S2A475KT000N
footprint CAP-1812 (1812 (4532M) Capacitor)
pins: 1, 2

## C4532X7T2E105KT000N
designator C?  Capacitance: 1uF  (hidden comment: *)
Capacitor, Ceramic (MLCC), 1uF, ±10%, 250V, X7T, ±10%, SMD 1812; Manufacturer: TDK; Manufacturer Part Number: C4532X7T2E105KT000N
footprint CAP-1812 (1812 (4532M) Capacitor)
pins: 1, 2

## C4532X7T2W474KT000N
designator C?  Capacitance: 470nF  (hidden comment: *)
Capacitor, Ceramic (MLCC), 470nF, ±10%, 450V, X7T, ±10%, SMD 1812; Manufacturer: TDK; Manufacturer Part Number: C4532X7T2W474KT000N
footprint CAP-1812 (1812 (4532M) Capacitor)
pins: 1, 2

## CC1812JKNPOCBN471
designator C?  Capacitance: 470pF  (hidden comment: *)
Capacitor, Ceramic (MLCC), 470pF, ±5%, 1kV, NP0, ±5%, SMD 1812; Manufacturer: YAGEO; Manufacturer Part Number: CC1812JKNPOCBN471
footprint CAP-1812 (1812 (4532M) Capacitor)
pins: 1, 2

## CC1812KKX7R0BB224
designator C?  Capacitance: 220nF  (hidden comment: *)
Capacitor, Ceramic (MLCC), 220nF, ±10%, 100V, X7R, ±10%, SMD 1812; Manufacturer: YAGEO; Manufacturer Part Number: CC1812KKX7R0BB224
footprint CAP-1812 (1812 (4532M) Capacitor)
pins: 1, 2

## CC1812KKX7R0BB474
designator C?  Capacitance: 470nF  (hidden comment: *)
Capacitor, Ceramic (MLCC), 470nF, ±10%, 100V, X7R, ±10%, SMD 1812; Manufacturer: YAGEO; Manufacturer Part Number: CC1812KKX7R0BB474
footprint CAP-1812 (1812 (4532M) Capacitor)
pins: 1, 2

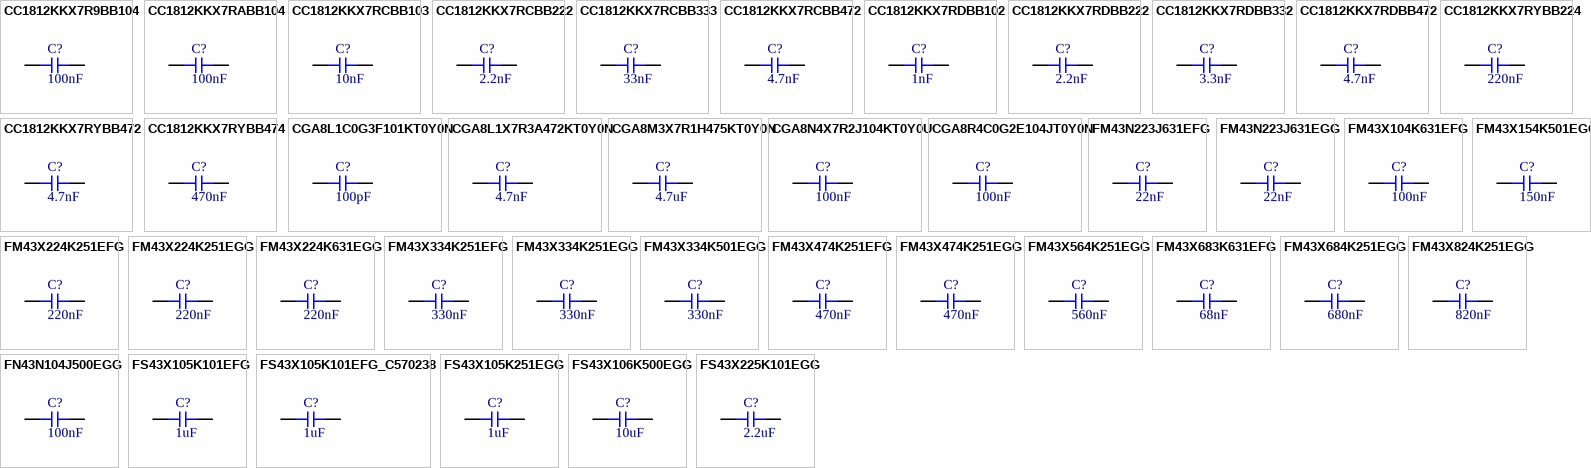
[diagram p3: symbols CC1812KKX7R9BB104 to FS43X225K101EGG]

## CC1812KKX7R9BB104
designator C?  Capacitance: 100nF  (hidden comment: *)
Capacitor, Ceramic (MLCC), 100nF, ±10%, 50V, X7R, ±10%, SMD 1812; Manufacturer: YAGEO; Manufacturer Part Number: CC1812KKX7R9BB104
footprint CAP-1812 (1812 (4532M) Capacitor)
pins: 1, 2

## CC1812KKX7RABB104
designator C?  Capacitance: 100nF  (hidden comment: *)
Capacitor, Ceramic (MLCC), 100nF, ±10%, 200V, X7R, ±10%, SMD 1812; Manufacturer: YAGEO; Manufacturer Part Number: CC1812KKX7RABB104
footprint CAP-1812 (1812 (4532M) Capacitor)
pins: 1, 2

## CC1812KKX7RCBB103
designator C?  Capacitance: 10nF  (hidden comment: *)
Capacitor, Ceramic (MLCC), 10nF, ±10%, 1kV, X7R, ±10%, SMD 1812; Manufacturer: YAGEO; Manufacturer Part Number: CC1812KKX7RCBB103
footprint CAP-1812 (1812 (4532M) Capacitor)
pins: 1, 2

## CC1812KKX7RCBB222
designator C?  Capacitance: 2.2nF  (hidden comment: *)
Capacitor, Ceramic (MLCC), 2.2nF, ±10%, 1kV, X7R, ±10%, SMD 1812; Manufacturer: YAGEO; Manufacturer Part Number: CC1812KKX7RCBB222
footprint CAP-1812 (1812 (4532M) Capacitor)
pins: 1, 2

## CC1812KKX7RCBB333
designator C?  Capacitance: 33nF  (hidden comment: *)
Capacitor, Ceramic (MLCC), 33nF, ±10%, 1kV, X7R, ±10%, SMD 1812; Manufacturer: YAGEO; Manufacturer Part Number: CC1812KKX7RCBB333
footprint CAP-1812 (1812 (4532M) Capacitor)
pins: 1, 2

## CC1812KKX7RCBB472
designator C?  Capacitance: 4.7nF  (hidden comment: *)
Capacitor, Ceramic (MLCC), 4.7nF, ±10%, 1kV, X7R, ±10%, SMD 1812; Manufacturer: YAGEO; Manufacturer Part Number: CC1812KKX7RCBB472
footprint CAP-1812 (1812 (4532M) Capacitor)
pins: 1, 2

## CC1812KKX7RDBB102
designator C?  Capacitance: 1nF  (hidden comment: *)
Capacitor, Ceramic (MLCC), 1nF, ±10%, 2kV, X7R, ±10%, SMD 1812; Manufacturer: YAGEO; Manufacturer Part Number: CC1812KKX7RDBB102
footprint CAP-1812 (1812 (4532M) Capacitor)
pins: 1, 2

## CC1812KKX7RDBB222
designator C?  Capacitance: 2.2nF  (hidden comment: *)
Capacitor, Ceramic (MLCC), 2.2nF, ±10%, 2kV, X7R, ±10%, SMD 1812; Manufacturer: YAGEO; Manufacturer Part Number: CC1812KKX7RDBB222
footprint CAP-1812 (1812 (4532M) Capacitor)
pins: 1, 2

## CC1812KKX7RDBB332
designator C?  Capacitance: 3.3nF  (hidden comment: *)
Capacitor, Ceramic (MLCC), 3.3nF, ±10%, 2kV, X7R, ±10%, SMD 1812; Manufacturer: YAGEO; Manufacturer Part Number: CC1812KKX7RDBB332
footprint CAP-1812 (1812 (4532M) Capacitor)
pins: 1, 2

## CC1812KKX7RDBB472
designator C?  Capacitance: 4.7nF  (hidden comment: *)
Capacitor, Ceramic (MLCC), 4.7nF, ±10%, 2kV, X7R, ±10%, SMD 1812; Manufacturer: YAGEO; Manufacturer Part Number: CC1812KKX7RDBB472
footprint CAP-1812 (1812 (4532M) Capacitor)
pins: 1, 2

## CC1812KKX7RYBB224
designator C?  Capacitance: 220nF  (hidden comment: *)
Capacitor, Ceramic (MLCC), 220nF, ±10%, 250V, X7R, ±10%, SMD 1812; Manufacturer: YAGEO; Manufacturer Part Number: CC1812KKX7RYBB224
footprint CAP-1812 (1812 (4532M) Capacitor)
pins: 1, 2

## CC1812KKX7RYBB472
designator C?  Capacitance: 4.7nF  (hidden comment: *)
Capacitor, Ceramic (MLCC), 4.7nF, ±10%, 250V, X7R, ±10%, SMD 1812; Manufacturer: YAGEO; Manufacturer Part Number: CC1812KKX7RYBB472
footprint CAP-1812 (1812 (4532M) Capacitor)
pins: 1, 2

## CC1812KKX7RYBB474
designator C?  Capacitance: 470nF  (hidden comment: *)
Capacitor, Ceramic (MLCC), 470nF, ±10%, 250V, X7R, ±10%, SMD 1812; Manufacturer: YAGEO; Manufacturer Part Number: CC1812KKX7RYBB474
footprint CAP-1812 (1812 (4532M) Capacitor)
pins: 1, 2

## CGA8L1C0G3F101KT0Y0N
designator C?  Capacitance: 100pF  (hidden comment: *)
Capacitor, Ceramic (MLCC), 100pF, ±10%, 3kV, C0G, ±10%, SMD 1812; Manufacturer: TDK; Manufacturer Part Number: CGA8L1C0G3F101KT0Y0N
footprint CAP-1812 (1812 (4532M) Capacitor)
pins: 1, 2

## CGA8L1X7R3A472KT0Y0N
designator C?  Capacitance: 4.7nF  (hidden comment: *)
Capacitor, Ceramic (MLCC), 4.7nF, ±10%, 1kV, X7R, ±10%, SMD 1812; Manufacturer: TDK; Manufacturer Part Number: CGA8L1X7R3A472KT0Y0N
footprint CAP-1812 (1812 (4532M) Capacitor)
pins: 1, 2

## CGA8M3X7R1H475KT0Y0N
designator C?  Capacitance: 4.7uF  (hidden comment: *)
Capacitor, Ceramic (MLCC), 4.7uF, ±10%, 50V, X7R, ±10%, SMD 1812; Manufacturer: TDK; Manufacturer Part Number: CGA8M3X7R1H475KT0Y0N
footprint CAP-1812 (1812 (4532M) Capacitor)
pins: 1, 2

## CGA8N4X7R2J104KT0Y0U
designator C?  Capacitance: 100nF  (hidden comment: *)
Capacitor, Ceramic (MLCC), 100nF, ±10%, 630V, X7R, ±10%, SMD 1812; Manufacturer: TDK; Manufacturer Part Number: CGA8N4X7R2J104KT0Y0U
footprint CAP-1812 (1812 (4532M) Capacitor)
pins: 1, 2

## CGA8R4C0G2E104JT0Y0N
designator C?  Capacitance: 100nF  (hidden comment: *)
Capacitor, Ceramic (MLCC), 100nF, ±5%, 250V, C0G, ±5%, SMD 1812; Manufacturer: TDK; Manufacturer Part Number: CGA8R4C0G2E104JT0Y0N
footprint CAP-1812 (1812 (4532M) Capacitor)
pins: 1, 2

## FM43N223J631EFG
designator C?  Capacitance: 22nF  (hidden comment: *)
Capacitor, Ceramic (MLCC), 22nF, ±5%, 630V, NP0, ±5%, SMD 1812; Manufacturer: PSA(Prosperity Dielectrics); Manufacturer Part Number: FM43N223J631EFG
footprint CAP-1812 (1812 (4532M) Capacitor)
pins: 1, 2

## FM43N223J631EGG
designator C?  Capacitance: 22nF  (hidden comment: *)
Capacitor, Ceramic (MLCC), 22nF, ±5%, 630V, NP0, ±5%, SMD 1812; Manufacturer: PSA(Prosperity Dielectrics); Manufacturer Part Number: FM43N223J631EGG
footprint CAP-1812 (1812 (4532M) Capacitor)
pins: 1, 2

## FM43X104K631EFG
designator C?  Capacitance: 100nF  (hidden comment: *)
Capacitor, Ceramic (MLCC), 100nF, ±10%, 630V, X7R, ±10%, SMD 1812; Manufacturer: PSA(Prosperity Dielectrics); Manufacturer Part Number: FM43X104K631EFG
footprint CAP-1812 (1812 (4532M) Capacitor)
pins: 1, 2

## FM43X154K501EGG
designator C?  Capacitance: 150nF  (hidden comment: *)
Capacitor, Ceramic (MLCC), 150nF, ±10%, 500V, ±10%, SMD 1812; Manufacturer: PSA(Prosperity Dielectrics); Manufacturer Part Number: FM43X154K501EGG
footprint CAP-1812 (1812 (4532M) Capacitor)
pins: 1, 2

## FM43X224K251EFG
designator C?  Capacitance: 220nF  (hidden comment: *)
Capacitor, Ceramic (MLCC), 220nF, ±10%, 250V, X7R, ±10%, SMD 1812; Manufacturer: PSA(Prosperity Dielectrics); Manufacturer Part Number: FM43X224K251EFG
footprint CAP-1812 (1812 (4532M) Capacitor)
pins: 1, 2

## FM43X224K251EGG
designator C?  Capacitance: 220nF  (hidden comment: *)
Capacitor, Ceramic (MLCC), 220nF, ±10%, 250V, X7R, ±10%, SMD 1812; Manufacturer: PSA(Prosperity Dielectrics); Manufacturer Part Number: FM43X224K251EGG
footprint CAP-1812 (1812 (4532M) Capacitor)
pins: 1, 2

## FM43X224K631EGG
designator C?  Capacitance: 220nF  (hidden comment: *)
Capacitor, Ceramic (MLCC), 220nF, ±10%, 630V, X7R, ±10%, SMD 1812; Manufacturer: PSA(Prosperity Dielectrics); Manufacturer Part Number: FM43X224K631EGG
footprint CAP-1812 (1812 (4532M) Capacitor)
pins: 1, 2

## FM43X334K251EFG
designator C?  Capacitance: 330nF  (hidden comment: *)
Capacitor, Ceramic (MLCC), 330nF, ±10%, 250V, X7R, ±10%, SMD 1812; Manufacturer: PSA(Prosperity Dielectrics); Manufacturer Part Number: FM43X334K251EFG
footprint CAP-1812 (1812 (4532M) Capacitor)
pins: 1, 2

## FM43X334K251EGG
designator C?  Capacitance: 330nF  (hidden comment: *)
Capacitor, Ceramic (MLCC), 330nF, ±10%, 250V, X7R, ±10%, SMD 1812; Manufacturer: PSA(Prosperity Dielectrics); Manufacturer Part Number: FM43X334K251EGG
footprint CAP-1812 (1812 (4532M) Capacitor)
pins: 1, 2

## FM43X334K501EGG
designator C?  Capacitance: 330nF  (hidden comment: *)
Capacitor, Ceramic (MLCC), 330nF, ±10%, 500V, X7R, ±10%, SMD 1812; Manufacturer: PSA(Prosperity Dielectrics); Manufacturer Part Number: FM43X334K501EGG
footprint CAP-1812 (1812 (4532M) Capacitor)
pins: 1, 2

## FM43X474K251EFG
designator C?  Capacitance: 470nF  (hidden comment: *)
Capacitor, Ceramic (MLCC), 470nF, ±10%, 250V, X7R, ±10%, SMD 1812; Manufacturer: PSA(Prosperity Dielectrics); Manufacturer Part Number: FM43X474K251EFG
footprint CAP-1812 (1812 (4532M) Capacitor)
pins: 1, 2

## FM43X474K251EGG
designator C?  Capacitance: 470nF  (hidden comment: *)
Capacitor, Ceramic (MLCC), 470nF, ±10%, 250V, X7R, ±10%, SMD 1812; Manufacturer: PSA(Prosperity Dielectrics); Manufacturer Part Number: FM43X474K251EGG
footprint CAP-1812 (1812 (4532M) Capacitor)
pins: 1, 2

## FM43X564K251EGG
designator C?  Capacitance: 560nF  (hidden comment: *)
Capacitor, Ceramic (MLCC), 560nF, ±10%, 250V, ±10%, SMD 1812; Manufacturer: PSA(Prosperity Dielectrics); Manufacturer Part Number: FM43X564K251EGG
footprint CAP-1812 (1812 (4532M) Capacitor)
pins: 1, 2

## FM43X683K631EFG
designator C?  Capacitance: 68nF  (hidden comment: *)
Capacitor, Ceramic (MLCC), 68nF, ±10%, 630V, X7R, ±10%, SMD 1812; Manufacturer: PSA(Prosperity Dielectrics); Manufacturer Part Number: FM43X683K631EFG
footprint CAP-1812 (1812 (4532M) Capacitor)
pins: 1, 2

## FM43X684K251EGG
designator C?  Capacitance: 680nF  (hidden comment: *)
Capacitor, Ceramic (MLCC), 680nF, ±10%, 250V, X7R, ±10%, SMD 1812; Manufacturer: PSA(Prosperity Dielectrics); Manufacturer Part Number: FM43X684K251EGG
footprint CAP-1812 (1812 (4532M) Capacitor)
pins: 1, 2

## FM43X824K251EGG
designator C?  Capacitance: 820nF  (hidden comment: *)
Capacitor, Ceramic (MLCC), 820nF, ±10%, 250V, X7R, ±10%, SMD 1812; Manufacturer: PSA(Prosperity Dielectrics); Manufacturer Part Number: FM43X824K251EGG
footprint CAP-1812 (1812 (4532M) Capacitor)
pins: 1, 2

## FN43N104J500EGG
designator C?  Capacitance: 100nF  (hidden comment: *)
Capacitor, Ceramic (MLCC), 100nF, ±5%, 50V, C0G, ±5%, SMD 1812; Manufacturer: PSA(Prosperity Dielectrics); Manufacturer Part Number: FN43N104J500EGG
footprint CAP-1812 (1812 (4532M) Capacitor)
pins: 1, 2

## FS43X105K101EFG
designator C?  Capacitance: 1uF  (hidden comment: *)
Capacitor, Ceramic (MLCC), 1uF, ±10%, 100V, X7R, ±10%, SMD 1812; Manufacturer: PSA(Prosperity Dielectrics); Manufacturer Part Number: FS43X105K101EFG
footprint CAP-1812 (1812 (4532M) Capacitor)
pins: 1, 2

## FS43X105K101EFG_C570238
designator C?  Capacitance: 1uF  (hidden comment: *)
Capacitor, Ceramic (MLCC), 1uF, ±10%, 100V, X7R, ±10%, SMD 1812; Manufacturer: PSA(Prosperity Dielectrics); Manufacturer Part Number: FS43X105K101EFG
footprint CAP-1812 (1812 (4532M) Capacitor)
pins: 1, 2

## FS43X105K251EGG
designator C?  Capacitance: 1uF  (hidden comment: *)
Capacitor, Ceramic (MLCC), 1uF, ±10%, 250V, X7R, ±10%, SMD 1812; Manufacturer: PSA(Prosperity Dielectrics); Manufacturer Part Number: FS43X105K251EGG
footprint CAP-1812 (1812 (4532M) Capacitor)
pins: 1, 2

## FS43X106K500EGG
designator C?  Capacitance: 10uF  (hidden comment: *)
Capacitor, Ceramic (MLCC), 10uF, ±10%, 50V, ±10%, SMD 1812; Manufacturer: PSA(Prosperity Dielectrics); Manufacturer Part Number: FS43X106K500EGG
footprint CAP-1812 (1812 (4532M) Capacitor)
pins: 1, 2

## FS43X225K101EGG
designator C?  Capacitance: 2.2uF  (hidden comment: *)
Capacitor, Ceramic (MLCC), 2.2uF, ±10%, 100V, X7R, ±10%, SMD 1812; Manufacturer: PSA(Prosperity Dielectrics); Manufacturer Part Number: FS43X225K101EGG
footprint CAP-1812 (1812 (4532M) Capacitor)
pins: 1, 2

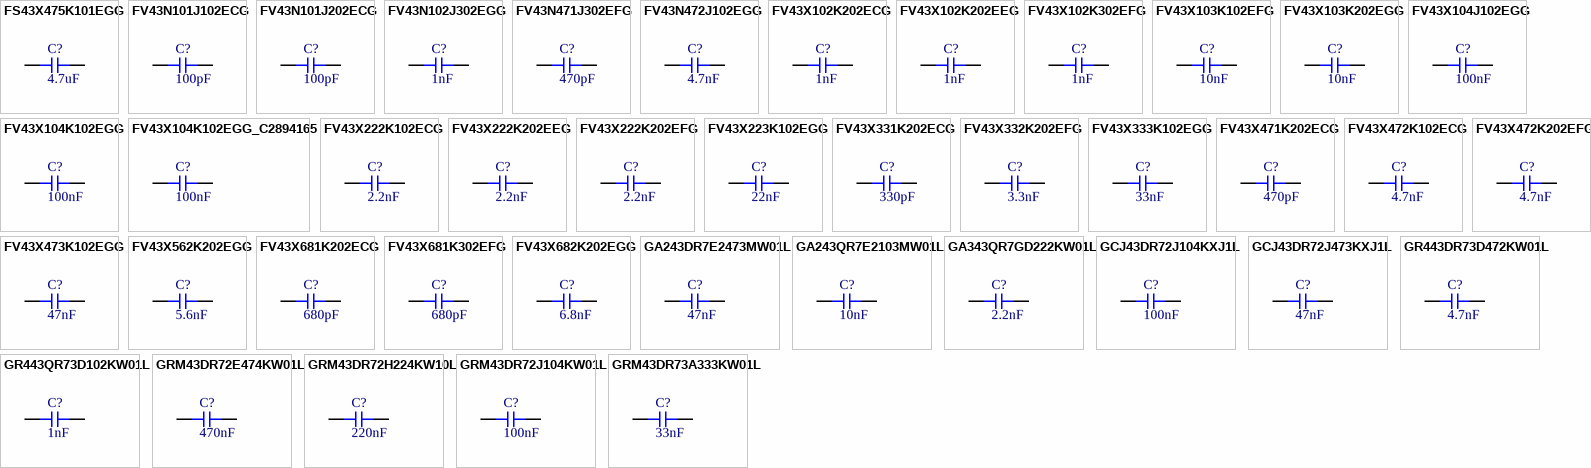
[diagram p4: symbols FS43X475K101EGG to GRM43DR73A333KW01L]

## FS43X475K101EGG
designator C?  Capacitance: 4.7uF  (hidden comment: *)
Capacitor, Ceramic (MLCC), 4.7uF, ±10%, 100V, X7R, ±10%, SMD 1812; Manufacturer: PSA(Prosperity Dielectrics); Manufacturer Part Number: FS43X475K101EGG
footprint CAP-1812 (1812 (4532M) Capacitor)
pins: 1, 2

## FV43N101J102ECG
designator C?  Capacitance: 100pF  (hidden comment: *)
Capacitor, Ceramic (MLCC), 100pF, ±5%, 1kV, C0G, ±5%, SMD 1812; Manufacturer: PSA(Prosperity Dielectrics); Manufacturer Part Number: FV43N101J102ECG
footprint CAP-1812 (1812 (4532M) Capacitor)
pins: 1, 2

## FV43N101J202ECG
designator C?  Capacitance: 100pF  (hidden comment: *)
Capacitor, Ceramic (MLCC), 100pF, ±5%, 2kV, C0G, ±5%, SMD 1812; Manufacturer: PSA(Prosperity Dielectrics); Manufacturer Part Number: FV43N101J202ECG
footprint CAP-1812 (1812 (4532M) Capacitor)
pins: 1, 2

## FV43N102J302EGG
designator C?  Capacitance: 1nF  (hidden comment: *)
Capacitor, Ceramic (MLCC), 1nF, ±5%, 3kV, C0G, ±5%, SMD 1812; Manufacturer: PSA(Prosperity Dielectrics); Manufacturer Part Number: FV43N102J302EGG
footprint CAP-1812 (1812 (4532M) Capacitor)
pins: 1, 2

## FV43N471J302EFG
designator C?  Capacitance: 470pF  (hidden comment: *)
Capacitor, Ceramic (MLCC), 470pF, ±5%, 3kV, NP0, ±5%, SMD 1812; Manufacturer: PSA(Prosperity Dielectrics); Manufacturer Part Number: FV43N471J302EFG
footprint CAP-1812 (1812 (4532M) Capacitor)
pins: 1, 2

## FV43N472J102EGG
designator C?  Capacitance: 4.7nF  (hidden comment: *)
Capacitor, Ceramic (MLCC), 4.7nF, ±5%, 1kV, NP0, ±5%, SMD 1812; Manufacturer: PSA(Prosperity Dielectrics); Manufacturer Part Number: FV43N472J102EGG
footprint CAP-1812 (1812 (4532M) Capacitor)
pins: 1, 2

## FV43X102K202ECG
designator C?  Capacitance: 1nF  (hidden comment: *)
Capacitor, Ceramic (MLCC), 1nF, ±10%, 2kV, ±10%, SMD 1812; Manufacturer: PSA(Prosperity Dielectrics); Manufacturer Part Number: FV43X102K202ECG
footprint CAP-1812 (1812 (4532M) Capacitor)
pins: 1, 2

## FV43X102K202EEG
designator C?  Capacitance: 1nF  (hidden comment: *)
Capacitor, Ceramic (MLCC), 1nF, ±10%, 2kV, X7R, ±10%, SMD 1812; Manufacturer: PSA(Prosperity Dielectrics); Manufacturer Part Number: FV43X102K202EEG
footprint CAP-1812 (1812 (4532M) Capacitor)
pins: 1, 2

## FV43X102K302EFG
designator C?  Capacitance: 1nF  (hidden comment: *)
Capacitor, Ceramic (MLCC), 1nF, ±10%, 3kV, X7R, ±10%, SMD 1812; Manufacturer: PSA(Prosperity Dielectrics); Manufacturer Part Number: FV43X102K302EFG
footprint CAP-1812 (1812 (4532M) Capacitor)
pins: 1, 2

## FV43X103K102EFG
designator C?  Capacitance: 10nF  (hidden comment: *)
Capacitor, Ceramic (MLCC), 10nF, ±10%, 1kV, X7R, ±10%, SMD 1812; Manufacturer: PSA(Prosperity Dielectrics); Manufacturer Part Number: FV43X103K102EFG
footprint CAP-1812 (1812 (4532M) Capacitor)
pins: 1, 2

## FV43X103K202EGG
designator C?  Capacitance: 10nF  (hidden comment: *)
Capacitor, Ceramic (MLCC), 10nF, ±10%, 2kV, X7R, ±10%, SMD 1812; Manufacturer: PSA(Prosperity Dielectrics); Manufacturer Part Number: FV43X103K202EGG
footprint CAP-1812 (1812 (4532M) Capacitor)
pins: 1, 2

## FV43X104J102EGG
designator C?  Capacitance: 100nF  (hidden comment: *)
Capacitor, Ceramic (MLCC), 100nF, ±5%, 1kV, X7R, ±5%, SMD 1812; Manufacturer: PSA(Prosperity Dielectrics); Manufacturer Part Number: FV43X104J102EGG
footprint CAP-1812 (1812 (4532M) Capacitor)
pins: 1, 2

## FV43X104K102EGG
designator C?  Capacitance: 100nF  (hidden comment: *)
Capacitor, Ceramic (MLCC), 100nF, ±10%, 1kV, X7R, ±10%, SMD 1812; Manufacturer: PSA(Prosperity Dielectrics); Manufacturer Part Number: FV43X104K102EGG
footprint CAP-1812 (1812 (4532M) Capacitor)
pins: 1, 2

## FV43X104K102EGG_C2894165
designator C?  Capacitance: 100nF  (hidden comment: *)
Capacitor, Ceramic (MLCC), 100nF, ±10%, 1kV, X7R, ±10%, SMD 1812; Manufacturer: PSA(Prosperity Dielectrics); Manufacturer Part Number: FV43X104K102EGG
footprint CAP-1812 (1812 (4532M) Capacitor)
pins: 1, 2

## FV43X222K102ECG
designator C?  Capacitance: 2.2nF  (hidden comment: *)
Capacitor, Ceramic (MLCC), 2.2nF, ±10%, 1kV, X7R, ±10%, SMD 1812; Manufacturer: PSA(Prosperity Dielectrics); Manufacturer Part Number: FV43X222K102ECG
footprint CAP-1812 (1812 (4532M) Capacitor)
pins: 1, 2

## FV43X222K202EEG
designator C?  Capacitance: 2.2nF  (hidden comment: *)
Capacitor, Ceramic (MLCC), 2.2nF, ±10%, 2kV, X7R, ±10%, SMD 1812; Manufacturer: PSA(Prosperity Dielectrics); Manufacturer Part Number: FV43X222K202EEG
footprint CAP-1812 (1812 (4532M) Capacitor)
pins: 1, 2

## FV43X222K202EFG
designator C?  Capacitance: 2.2nF  (hidden comment: *)
Capacitor, Ceramic (MLCC), 2.2nF, ±10%, 2kV, X7R, ±10%, SMD 1812; Manufacturer: PSA(Prosperity Dielectrics); Manufacturer Part Number: FV43X222K202EFG
footprint CAP-1812 (1812 (4532M) Capacitor)
pins: 1, 2

## FV43X223K102EGG
designator C?  Capacitance: 22nF  (hidden comment: *)
Capacitor, Ceramic (MLCC), 22nF, ±10%, 1kV, X7R, ±10%, SMD 1812; Manufacturer: PSA(Prosperity Dielectrics); Manufacturer Part Number: FV43X223K102EGG
footprint CAP-1812 (1812 (4532M) Capacitor)
pins: 1, 2

## FV43X331K202ECG
designator C?  Capacitance: 330pF  (hidden comment: *)
Capacitor, Ceramic (MLCC), 330pF, ±10%, 2kV, X7R, ±10%, SMD 1812; Manufacturer: PSA(Prosperity Dielectrics); Manufacturer Part Number: FV43X331K202ECG
footprint CAP-1812 (1812 (4532M) Capacitor)
pins: 1, 2

## FV43X332K202EFG
designator C?  Capacitance: 3.3nF  (hidden comment: *)
Capacitor, Ceramic (MLCC), 3.3nF, ±10%, 2kV, X7R, ±10%, SMD 1812; Manufacturer: PSA(Prosperity Dielectrics); Manufacturer Part Number: FV43X332K202EFG
footprint CAP-1812 (1812 (4532M) Capacitor)
pins: 1, 2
